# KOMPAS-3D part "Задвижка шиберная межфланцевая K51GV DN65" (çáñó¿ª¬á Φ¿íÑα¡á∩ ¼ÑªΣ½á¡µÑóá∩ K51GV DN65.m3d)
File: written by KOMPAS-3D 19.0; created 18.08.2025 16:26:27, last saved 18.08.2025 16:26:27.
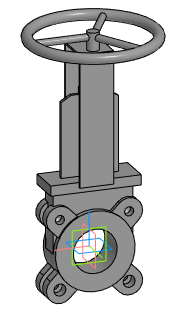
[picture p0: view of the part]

Document properties: Автор: Евгений; Полное имя файла: E:\Dendor Работа Сачек\3D для проектировщиков\2.4 Тип K51GV. Задвижка шиберная межфланцевая\stp_Задвижка шиберная K51GV DN50-400 с маховиком\Задвижка шиберная межфланцевая K51GV DN65.m3d

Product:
- Part/product: Задвижка шиберная межфланцевая K51GV DN65

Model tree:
1. Операция без истории:1  (labels: Задвижка шиберная межфланцевая K51GV DN65)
